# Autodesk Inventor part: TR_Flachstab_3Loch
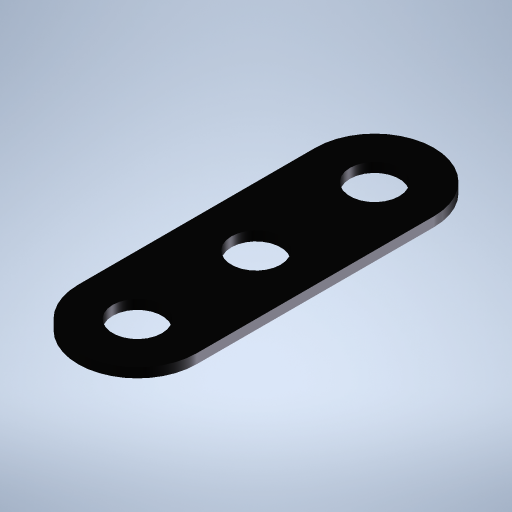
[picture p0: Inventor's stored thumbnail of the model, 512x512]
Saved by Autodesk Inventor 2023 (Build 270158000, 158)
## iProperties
Created: 2023-11
Part Number: TR_Flachstab_3Loch
Material: Edelstahl
Document SubType Name: Modeling
Designer: Admin
Density: 8 g/cm^3
Appearance: Halbpoliert
Author: Admin
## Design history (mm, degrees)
sketch "Skizze1"
  geometry: L1 (0, 10)-(0, -10); L2 (-5, 10)-(-5, -10); L3 (5, -10)-(5, 10); A1 r 5 centre (0, 10) between (5, 10) and (-5, 10); A2 r 5 centre (0, -10) between (-5, -10) and (5, -10); 3 further points
  constraints: 8 end point, 4 point on circle, 4 tangent, 2 centre point, 2 midpoint, 1 horizontal alignment, 1 parallel, 1 vertical, 1 vertical alignment
  dimensions: "d0" = 20 distance of L1.start L1.end (computed from Loch, Einheitsmaß); "d1" = 5 radius of A1 (= 0.5 x Einheitsmaß)
extrude "Extrusion1" new body sketch "Skizze1" distance "d5" = 0.8 (= Dicke); taper "d6" = 0 deg
sketch "Skizze2"
  geometry: C1 r 2.075 at (0, 10); A1 r 5 centre (0, 10) between (5, 10) and (-5, 10) reference; 1 further point
  constraints: 1 centre point, 1 coincident
  dimensions: "d7" = 4.15 diameter of C1 (= 2 x Radius)
extrude "Extrusion2" cut sketch "Skizze2" stored distance "d8" = 10; taper "d9" = 0 deg
pattern_linear "Rechteckige Anordnung1" dims "d12" = 10 (= Einheitsmaß)
node "Volumenkörper1"
other parameters: "Einheitsmaß" = 10 [user parameter; used in 3 equation terms], "Radius" = 2.075 [user parameter; used in 1 equation term], "Fasen" = 0.5 [user parameter], "Dicke" = 0.8 [user parameter; used in 1 equation term]
